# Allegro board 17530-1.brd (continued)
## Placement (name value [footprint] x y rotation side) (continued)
PC4514  SC1U50V3KX-1-GP  [C603H36]  71.53 40.74 270 top
PC4515  SC1500P50V2KX-2-DL-GP  [C402H22]  68.31 59.99 270 top
PC4516  SC10U25V5KX-DL-GP  [C805H58]  92.71 38.61 180 top
PC4517  SC10U25V5KX-DL-GP  [C805H58]  94.74 38.61 180 top
PC4518  SCD1U50V3KX-DL-GP  [C603H35]  92.35 45.06 90 top
PC4519  SC1U50V3KX-1-GP  [C603H36]  89.31 39.73 270 top
PC4520  SC1500P50V2KX-2-DL-GP  [C402H22]  85.22 59.82 270 top
PC4601  SC10U25V5KX-DL-GP  [C805H58]  8.28 79.48 90 top
PC4602  SC10U25V5KX-DL-GP  [C805H58]  8.28 81.64 90 top
PC4603  SCD1U50V3KX-DL-GP  [C603H35]  14.58 79.58 0 top
PC4604  SC1U50V3KX-1-GP  [C603H36]  12.32 74.98 270 top
PC4605  SC1500P50V2KX-2-DL-GP  [C402H22]  16.43 77.9 0 top
PC4606  SC10U25V5KX-DL-GP  [C805H58]  8.56 108.56 90 top
PC4607  SC10U25V5KX-DL-GP  [C805H58]  8.56 110.57 90 top
PC4608  SCD1U50V3KX-DL-GP  [C603H35]  21.77 114.45 270 top
PC4609  SC1U50V3KX-1-GP  [C603H36]  16.74 117.93 180 top
PC4610  SC1500P50V2KX-2-DL-GP  [C402H22]  23.19 108.76 180 top
PC4701  SC1U50V3KX-1-GP  [C603H36]  127.51 41.53 90 top
PC4702  SC10U25V5KX-DL-GP  [C805H58]  127.13 37.85 90 top
PC4703  SC10U25V5KX-DL-GP  [C805H58]  127.13 39.88 90 top
PC4704  SCD1U50V3KX-DL-GP  [C603H35]  134.49 50.8 0 top
PC4705  SC1U50V3KX-1-GP  [C603H36]  114.43 41.15 0 top
PC4706  SC1U50V3KX-1-GP  [C603H36]  133.22 50.8 0 top
PC4707  SC1500P50V2KX-2-DL-GP  [C402H22]  122.94 51.44 90 top
PC4708  SC18P50V2JN-1DLGP  [C402H22]  135 61.87 0 top
PC4801  SC10U10V5KX-2DLGP  [C805H50]  126.11 89.43 90 top
PC4802  SC10U10V5KX-2DLGP  [C805H50]  126.14 87.4 90 top
PC4803  SCD1U16V2KX-3DLGP  [C402H22]  126.29 90.91 90 top
PC4804  SC1U50V3KX-1-GP  [C603H36]  122.66 74.68 180 top
PC4805  SCD047U25V2KX-4-GP  [C402H22]  128.91 75.44 90 top
PC4806  SCD01U50V2KX-1DLGP  [C402H22]  124.97 82.55 270 top
PC4807  SC1KP50V2KX-1DLGP  [C402H22]  128.52 73.94 0 top
PC4808  SC22U6D3V5MX-2DLGP  [C805H54]  125.02 80.06 90 top
PC4809  SC22U6D3V5MX-2DLGP  [C805H54]  125.02 78.03 90 top
PC4810  SCD1U16V2KX-3DLGP  [C402H22]  124.97 81.53 90 top
PC4811  SCD047U25V2KX-4-GP  [C402H22]  129.08 71.53 270 top
PC4812  SC2200P50V2KX-2DLGP  [C402H22]  129.11 72.47 270 top
PC4901  SC10U25V5KX-DL-GP  [C805H58]  22.25 203.24 270 top
PC4902  SC10U25V5KX-DL-GP  [C805H58]  30.2 210.64 90 top
PC4903  SC10U25V5KX-DL-GP  [C805H58]  30.18 212.62 90 top
PC4904  SC10U25V5KX-DL-GP  [C805H58]  22.23 205.49 270 top
PC4905  SC10U25V5KX-DL-GP  [C805H58]  30.2 208.65 90 top
PC4906  SCD1U50V3KX-DL-GP  [C603H35]  17.48 201.96 90 top
PC4907  SCD1U50V3KX-DL-GP  [C603H35]  11.63 198.5 0 top
PC4908  SCD1U50V3KX-DL-GP  [C603H35]  16 210.16 270 top
PC4909  SC1U50V3KX-1-GP  [C603H36]  21.69 177.83 270 top
PC4910  SC1U50V3KX-1-GP  [C603H36]  24.04 231.53 180 top
PC4911  SC1KP50V2KX-1DLGP  [C402H22]  31.88 191.85 90 top
PC4912  SC1KP50V2KX-1DLGP  [C402H22]  26.54 214.88 90 top
PC4913  SCD1U16V2KX-3DLGP  [C402H22]  16.59 204.27 90 top
PC4914  SC22P50V2JN-4DLGP  [C402H22]  7.72 200.46 90 top
PC4915  SC22P50V2JN-4DLGP  [C402H22]  7.06 205.64 0 top
PC4916  SC1U50V3KX-1-GP  [C603H36]  8 204.09 270 top
PC4917  SC1U50V3KX-1-GP  [C603H36]  17.5 203.15 90 top
PC4918  SCD22U10V2KX-2-GP  [C402H22]  10.54 196.39 90 top
PC4919  SCD22U10V2KX-2-GP  [C402H22]  12.14 208.69 180 top
PC5001  SC1U50V3KX-1-GP  [C603H36]  46.63 175.77 90 top
PC5002  SC1U50V3KX-1-GP  [C603H36]  45.85 177.77 180 top
PC5003  SC1U50V3KX-1-GP  [C603H36]  49.58 179.58 270 top
PC5004  SC10U25V5KX-DL-GP  [C805H58]  49.66 187.32 270 top
PC5005  SC10U25V5KX-DL-GP  [C805H58]  49.66 185.29 270 top
PC5006  SC10U25V5KX-DL-GP  [C805H58]  49.66 183.26 270 top
PC5007  SC10U25V5KX-DL-GP  [C805H58]  49.66 181.23 270 top
PC5008  SCD1U50V3KX-DL-GP  [C603H35]  45.36 182.55 0 top
PC5009  SC10U10V5KX-2DLGP  [C805H50]  39.12 183.46 270 top
PC5010  SC1U50V3KX-1-GP  [C603H36]  64.8 174.29 270 top
PC5011  SC10U10V5KX-2DLGP  [C805H50]  36.32 179.2 270 top
PC5012  SC10U10V5KX-2DLGP  [C805H50]  36.32 181.23 270 top
PC5013  SC18P50V2JN-1DLGP  [C402H22]  37.97 174.85 0 top
PC5014  SC1500P50V2KX-2-DL-GP  [C402H22]  55.35 180.57 270 top
PC5015  SCD047U25V2KX-4-GP  [C402H22]  38.58 177.5 0 top
PC5101  SC1U50V3KX-1-GP  [C603H36]  193.17 176.66 90 top
PC5102  SC10U25V5KX-DL-GP  [C805H58]  193.55 168.91 90 top
PC5103  SC10U25V5KX-DL-GP  [C805H58]  193.55 170.94 90 top
PC5104  SC10U25V5KX-DL-GP  [C805H58]  193.55 172.97 90 top
PC5105  SC10U25V5KX-DL-GP  [C805H58]  193.55 175.01 90 top
PC5106  SCD1U50V3KX-DL-GP  [C603H35]  192.53 180.47 90 top
PC5107  SC1U50V3KX-1-GP  [C603H36]  194.56 151.64 90 top
PC5108  SC18P50V2JN-1DLGP  [C402H22]  191.24 188.49 90 top
PC5109  SC1U50V3KX-1-GP  [C603H36]  189.87 180.47 270 top
PC5110  SC1500P50V2KX-2-DL-GP  [C402H22]  183.82 165.79 180 top
PC5201  SC10U10V5KX-2DLGP  [C805H50]  103.38 175.51 270 top
PC5202  SC1U50V3KX-1-GP  [C603H36]  103 173.86 270 top
PC5203  SC10U10V5KX-2DLGP  [C805H50]  116.59 175.77 180 top
PC5204  SC10U10V5KX-2DLGP  [C805H50]  114.55 175.77 180 top
PC5205  SCD1U16V2KX-3DLGP  [C402H22]  104.52 171.83 270 top
PC5206  SC150P50V2JN-3GP  [C402H22]  114.27 172.34 180 top
PG4501  GAP-CLOSE-PWR-3-GP  [GAP-CLOSE-PWR-3]  41.02 44.32 90 bottom
PG4502  GAP-CLOSE-PWR-3-GP  [GAP-CLOSE-PWR-3]  41 45.75 270 bottom
PG4503  GAP-CLOSE-PWR-3-GP  [GAP-CLOSE-PWR-3]  53.62 51.28 135 bottom
PG4504  GAP-CLOSE-PWR-3-GP  [GAP-CLOSE-PWR-3]  54.33 51.97 135 bottom
PG4505  GAP-CLOSE-PWR-3-GP  [GAP-CLOSE-PWR-3]  72.44 55.47 135 bottom
PG4506  GAP-CLOSE-PWR-3-GP  [GAP-CLOSE-PWR-3]  73.2 56.24 135 bottom
PG4507  GAP-CLOSE-PWR-3-GP  [GAP-CLOSE-PWR-3]  97.08 52.27 90 bottom
PG4508  GAP-CLOSE-PWR-3-GP  [GAP-CLOSE-PWR-3]  97.03 53.9 270 bottom
PG4601  GAP-CLOSE-PWR-3-GP  [GAP-CLOSE-PWR-3]  20.95 85.34 0 bottom
PG4602  GAP-CLOSE-PWR-3-GP  [GAP-CLOSE-PWR-3]  22.48 85.34 180 bottom
PG4603  GAP-CLOSE-PWR-3-GP  [GAP-CLOSE-PWR-3]  20.42 96.29 0 bottom
PG4604  GAP-CLOSE-PWR-3-GP  [GAP-CLOSE-PWR-3]  22.3 96.29 180 bottom
PG4701  GAP-CLOSE-PWR-3-GP  [GAP-CLOSE-PWR-3]  133.38 64.26 90 top
PG4901  GAP-CLOSE-PWR-3-GP  [GAP-CLOSE-PWR-3]  23.16 224.48 90 bottom
PG4902  GAP-CLOSE-PWR-3-GP  [GAP-CLOSE-PWR-3]  6.99 199.26 270 top
PG4903  GAP-CLOSE-PWR-2U-GP  [GAP-CLOSE-PWR-2U]  18.21 204.24 0 top
PG5005  GAP-CLOSE-PWR-3-GP  [GAP-CLOSE-PWR-3]  36.58 176.91 0 top
PG5006  GAP-CLOSE-PWR-3-GP  [GAP-CLOSE-PWR-3]  36.58 177.67 0 top
PL4501  COIL-D36UH-19-GP  [RT-D6D3-1D4-103065H394]  42.82 44.93 270 top
PL4502  COIL-D36UH-19-GP  [RT-D6D3-1D4-103065H394]  61.24 49.62 270 top
PL4503  COIL-D36UH-19-GP  [RT-D6D3-1D4-103065H394]  79.57 53.29 270 top
PL4504  COIL-D36UH-19-GP  [RT-D6D3-1D4-103065H394]  98.09 53.16 270 top
PL4601  COIL-D36UH-19-GP  [RT-D6D3-1D4-103065H394]  21.02 87.53 180 top
PL4602  COIL-D36UH-19-GP  [RT-D6D3-1D4-103065H394]  21.18 98.45 180 top
PL4701  IND-D47UH-22-GP-U  [L7066-1830-UH119]  118.11 46.48 270 top
PL4901  IND-2D2UH-356-GP  [RT-D6D6-6D6-108108H426]  20.7 192.53 90 top
PL4902  IND-2D2UH-356-GP  [RT-D6D6-6D6-108108H426]  15.39 220.78 90 top
PL4903  MHC2012S800UBP-GP  [L805H44]  46.79 199.47 270 top
PL4904  MHC2012S800UBP-GP  [L805H44]  46.79 201.5 270 top
PL4905  MHC2012S800UBP-GP  [L805H44]  46.79 203.53 270 top
PL5001  COIL-1D2UH-50-GP  [RT-D6D4-1D9-103072H394]  67.26 179.53 180 top
PL5002  MHC2012S800UBP-GP  [L805H44]  52.02 190.96 180 top
PL5003  MHC2012S800UBP-GP  [L805H44]  54.81 190.96 180 top
PL5101  IND-1D5UH-52-GP  [L115100-2030H158]  190.37 159.13 0 top
PL5104  MHC2012S800UBP-GP  [L805H44]  188.47 175.61 180 top
PL5105  MHC2012S800UBP-GP  [L805H44]  190.75 175.61 180 top
PR4401  2D2R3-1-U-GP  [R603H22]  17.78 67.04 90 top
PR4402  1KR2F-3-GP  [R402H16]  16.66 70.76 0 top
PR4403  26K1R2F-2-GP  [R402H16]  16.99 50.39 0 top
PR4404  100R2F-L1-GP-U  [R402H14]  22.29 67.89 0 top
PR4405  45D3R2F-L-GP  [R402H16]  20.26 67.89 0 top
PR4406  75R2F-2-GP  [R402H16]  21.27 67.89 0 top
PR4407  47R2F-GP  [R402H16]  27.38 62.74 90 top
PR4408  4K02R2F-GP  [R402H16]  27.41 60.76 90 top
PR4409  1KR2F-3-GP  [R402H16]  25.81 62.23 0 top
PR4410  10R2F-L-GP  [R402H14]  20.78 65.61 180 top
PR4411  49D9R2F-GP  [R402H16]  19.66 65.63 180 top
PR4412  100KR2F-L1-GP  [R402H16]  23.62 49.78 270 top
PR4413  10KR2F-2-GP  [R402H16]  20.19 49.5 0 top
PR4414  6K98R2F-GP  [R402H16]  25.15 47.88 180 top
PR4415  100KR2F-L1-GP  [R402H16]  25.15 51.05 0 top
PR4416  100R2F-L1-GP-U  [R402H14]  26.95 63.78 270 top
PR4417  6K98R2F-GP  [R402H16]  26.72 50.62 270 top
PR4418  0R0402-PAD-2-GP  [0R0402-PAD-1]  25.02 63.71 270 top
PR4419  100KR2F-L1-GP  [R402H16]  25.2 52.96 0 top
PR4420  3KR2F-GP  [R402H16]  24.99 66.53 270 top
PR4421  6K98R2F-GP  [R402H16]  27.69 53.31 270 top
PR4422  100KR2F-L1-GP  [R402H16]  25.2 54.86 0 top
PR4423  100R2F-L1-GP-U  [R402H14]  26.9 66.52 90 top
PR4424  10KR2F-2-GP  [R402H16]  19.15 49.5 0 top
PR4425  6K98R2F-GP  [R402H16]  29.26 55.45 180 top
PR4426  100KR2F-L1-GP  [R402H16]  27.43 48.64 0 top
PR4427  100KR2F-L1-GP  [R402H16]  27.79 57.97 90 top
PR4428  270KR2F-GP  [R402H16]  27.79 56.95 270 top
PR4429  100KR2F-L1-GP  [R402H16]  29.59 52.31 270 top
PR4430  30KR2F-GP  [R402H16]  21.87 65.59 180 top
PR4431  NTC-100K-20-GP  [NTC-402H24-U]  39.47 51.66 270 top
PR4432  100KR2F-L1-GP  [R402H16]  29.59 53.32 270 top
PR4433  35K7R2F-GP  [R402H16]  24.51 58.55 180 top
PR4434  100KR2F-L1-GP  [R402H16]  30.56 54.99 180 top
PR4435  10R2F-L-GP  [R402H14]  23.14 47.55 180 top
PR4436  10R2F-L-GP  [R402H14]  26.37 48.97 180 top
PR4437  10R2F-L-GP  [R402H14]  27.69 52.27 270 top
PR4438  10R2F-L-GP  [R402H14]  27.64 54.43 270 top
PR4439  47R2F-GP  [R402H16]  10.08 65.35 270 top
PR4440  4K02R2F-GP  [R402H16]  11.35 62.18 270 top
PR4441  10KR2F-2-GP  [R402H16]  15.93 50.42 0 top
PR4442  1KR2F-3-GP  [R402H16]  10.57 63.86 0 top
PR4443  100KR2F-L1-GP  [R402H16]  11.86 54.13 0 top
PR4444  6K98R2F-GP  [R402H16]  10.59 55.04 0 top
PR4445  100R2F-L1-GP-U  [R402H14]  13.18 70.38 270 top
PR4446  100KR2F-L1-GP  [R402H16]  11.89 52.22 0 top
PR4447  0R0402-PAD-2-GP  [0R0402-PAD-1]  12.4 63.97 90 top
PR4448  6K98R2F-GP  [R402H16]  10.16 51.67 90 top
PR4449  68K1R3F-1-GP  [R603]  9.5 58.14 90 top
PR4450  3K6R2F-GP  [R402H16]  12.32 66.88 90 top
PR4451  100KR2F-L1-GP  [R402H16]  9.4 61.47 270 top
PR4452  261KR2F-GP  [R402H16]  8.86 59.72 0 top
PR4453  68K1R3F-1-GP  [R603]  8.86 56.06 0 top
PR4454  100R2F-L1-GP-U  [R402H14]  13.28 68.05 90 top
PR4455  NTC-100K-20-GP  [NTC-402H24-U]  25.1 82.65 90 top
PR4456  133KR2F-GP  [R402H16]  18.11 49.5 0 top
PR4457  24K9R2F-L-GP  [R402H16]  12.24 58.67 180 top
PR4458  42K2R2F-L-GP  [R402H16]  14.27 66.93 270 top
PR4459  10R2F-L-GP  [R402H14]  10.08 53.14 180 top
PR4460  10R2F-L-GP  [R402H14]  10.74 50.5 90 top
PR4461  75R2F-2-GP  [R402H16]  15.75 66.4 0 top
PR4462  2KR2F-3-GP  [R402H16]  18.16 65.93 90 top
PR4463  499R2F-2-GP  [R402H16]  12.95 49.91 0 top
PR4464  499R2F-2-GP  [R402H16]  22.12 49.48 0 top
PR4465  47K5R2F-GP  [R402H16]  14.88 50.42 0 top
PR4466  NTC-100K-20-GP  [NTC-402H24-U]  40.01 32.89 180 top
PR4467  38K3R2F-GP  [R402H16]  14.48 48.9 90 top
PR4468  NTC-100K-20-GP  [NTC-402H24-U]  12.12 82.17 90 top
PR4469  38K3R2F-GP  [R402H16]  21.67 47.98 270 top
PR4471  20KR2F-L-GP  [R402H16]  17.45 64.85 270 top
PR4501  2D2R5F-2-GP  [R805H24]  33.81 36.32 90 top
PR4503  10KR2J-3-GP  [R402H16]  39.52 38.07 270 top
PR4504  1R5J-2-GP  [R805H24]  39.52 35.79 180 top
PR4505  2D2R5F-2-GP  [R805H24]  32.77 51.56 270 top
PR4506  51R2F-2-GP  [R402H16]  30.76 34.42 90 top
PR4507  2D2R5F-2-GP  [R805H24]  51.97 40.49 90 top
PR4509  10KR2J-3-GP  [R402H16]  57.94 42.9 270 top
PR4510  1R5J-2-GP  [R805H24]  57.94 40.49 180 top
PR4511  2D2R5F-2-GP  [R805H24]  52.81 55.68 270 top
PR4512  51R2F-2-GP  [R402H16]  49.17 39.22 90 top
PR4514  2D2R5F-2-GP  [R805H24]  70.74 45.44 90 top
PR4515  10KR2J-3-GP  [R402H16]  76.48 46.46 270 top
PR4516  1R5J-2-GP  [R805H24]  76.48 44.04 180 top
PR4517  2D2R5F-2-GP  [R805H24]  71.09 60.53 270 top
PR4518  51R2F-2-GP  [R402H16]  68.86 43.92 90 top
PR4520  2D2R5F-2-GP  [R805H24]  89.18 44.68 90 top
PR4521  10KR2J-3-GP  [R402H16]  94.77 46.33 270 top
PR4522  1R5J-2-GP  [R805H24]  94.77 43.92 180 top
PR4523  2D2R5F-2-GP  [R805H24]  88.01 59.82 270 top
PR4524  51R2F-2-GP  [R402H16]  85.7 43 90 top
PR4525  2D2R5F-2-GP  [R805H24]  31.09 32.87 90 top
PR4526  2D2R5F-2-GP  [R805H24]  49.05 37.44 90 top
PR4527  2D2R5F-2-GP  [R805H24]  71.63 38.99 270 top
PR4528  2D2R5F-2-GP  [R805H24]  86.13 41.38 90 top
PR4601  2D2R5F-2-GP  [R805H24]  11.96 79.83 90 top
PR4603  10KR2J-3-GP  [R402H16]  14.15 90.32 180 top
PR4604  1R5J-2-GP  [R805H24]  11.73 90.32 90 top
PR4605  2D2R5F-2-GP  [R805H24]  16.21 80.77 0 top
PR4606  51R2F-2-GP  [R402H16]  10.46 73.99 180 top
PR4608  2D2R5F-2-GP  [R805H24]  21.62 116.89 0 top
PR4609  10KR2J-3-GP  [R402H16]  13.87 108.18 90 top
PR4610  1R5J-2-GP  [R805H24]  13.84 110.59 0 top
PR4611  2D2R5F-2-GP  [R805H24]  23.16 105.94 180 top
PR4612  51R2F-2-GP  [R402H16]  19.33 120.45 0 top
PR4613  2D2R5F-2-GP  [R805H24]  14.61 72.75 270 top
PR4614  2D2R5F-2-GP  [R805H24]  17.81 121.72 0 top
PR4701  GAP-CLOSE-PWR-3-GP  [GAP-CLOSE-PWR-3]  123.75 41.1 180 top
PR4702  GAP-CLOSE-PWR-3-GP  [GAP-CLOSE-PWR-3]  123.75 40.34 180 top
PR4703  GAP-CLOSE-PWR-3-GP  [GAP-CLOSE-PWR-3]  123.75 39.57 180 top
PR4704  GAP-CLOSE-PWR-3-GP  [GAP-CLOSE-PWR-3]  123.75 38.81 180 top
PR4705  GAP-CLOSE-PWR-3-GP  [GAP-CLOSE-PWR-3]  123.75 38.05 180 top
PR4706  GAP-CLOSE-PWR-3-GP  [GAP-CLOSE-PWR-3]  123.75 37.29 180 top
PR4707  2D2R5J-1-GP  [R805H24]  118.75 41.53 270 top
PR4708  40K2R2F-GP  [R402H16]  137.67 59.69 180 top
PR4709  2D2R5J-1-GP  [R805H24]  136.14 50.8 0 top
PR4710  10KR2J-3-GP  [R402H16]  121.16 41.53 0 top
PR4711  470KR2F-GP  [R402H16]  133.99 61.87 180 top
PR4712  2D2R5J-1-GP  [R805H24]  131.57 50.55 0 top
PR4713  2D2R5J-1-GP  [R805H24]  120.14 51.44 90 top
PR4714  4K87R2F-GP  [R402H16]  136.14 61.87 0 top
PR4715  10R2F-L-GP  [R402H14]  135 63.98 90 top
PR4716  10KR2F-2-GP  [R402H16]  137.29 61.87 180 top
PR4717  10R2F-L-GP  [R402H14]  136.91 63.98 90 top
PR4801  GAP-CLOSE-PWR-3-GP  [GAP-CLOSE-PWR-3]  120.32 92.25 90 top
PR4802  GAP-CLOSE-PWR-3-GP  [GAP-CLOSE-PWR-3]  121.08 92.25 90 top
PR4803  GAP-CLOSE-PWR-3-GP  [GAP-CLOSE-PWR-3]  121.97 92.25 90 top
PR4804  GAP-CLOSE-PWR-3-GP  [GAP-CLOSE-PWR-3]  122.73 92.25 90 top
PR4805  GAP-CLOSE-PWR-3-GP  [GAP-CLOSE-PWR-3]  125.02 92.25 90 top
PR4806  GAP-CLOSE-PWR-3-GP  [GAP-CLOSE-PWR-3]  123.49 92.25 90 top
PR4807  GAP-CLOSE-PWR-3-GP  [GAP-CLOSE-PWR-3]  125.78 92.25 90 top
PR4808  10R2F-L-GP  [R402H14]  122.66 72.26 180 top
PR4809  GAP-CLOSE-PWR-3-GP  [GAP-CLOSE-PWR-3]  124.26 92.25 90 top
PR4810  100R5J-4-GP  [R805H24]  126.24 84.61 90 top
PR4811  2K2R2F-GP  [R402H16]  129.54 73.94 0 top
PR4812  0R0402-PAD-2-GP  [0R0402-PAD-1]  124.26 70.92 270 top
PR4813  10R2F-L-GP  [R402H14]  129.03 69.37 90 top
PR4814  4K7R2F-GP  [R402H16]  129.01 70.51 90 top
PR4815  10R2F-L-GP  [R402H14]  117.22 90.42 180 top
PR4816  24KR2F-GP  [R402H16]  126.39 70.94 270 top
PR4901  GAP-CLOSE-PWR-3-GP  [GAP-CLOSE-PWR-3]  28.32 179.45 180 top
PR4902  GAP-CLOSE-PWR-3-GP  [GAP-CLOSE-PWR-3]  28.32 180.21 180 top
PR4903  GAP-CLOSE-PWR-3-GP  [GAP-CLOSE-PWR-3]  28.32 180.97 180 top
PR4904  GAP-CLOSE-PWR-3-GP  [GAP-CLOSE-PWR-3]  28.32 181.74 180 top
PR4905  GAP-CLOSE-PWR-3-GP  [GAP-CLOSE-PWR-3]  28.32 182.5 180 top
PR4906  GAP-CLOSE-PWR-3-GP  [GAP-CLOSE-PWR-3]  28.32 183.26 180 top
PR4908  GAP-CLOSE-PWR-3-GP  [GAP-CLOSE-PWR-3]  28.32 178.69 180 top
PR4910  GAP-CLOSE-PWR-3-GP  [GAP-CLOSE-PWR-3]  28.32 189.36 180 top
PR4912  GAP-CLOSE-PWR-3-GP  [GAP-CLOSE-PWR-3]  28.32 188.59 180 top
PR4914  GAP-CLOSE-PWR-3-GP  [GAP-CLOSE-PWR-3]  28.32 187.83 180 top
PR4916  GAP-CLOSE-PWR-3-GP  [GAP-CLOSE-PWR-3]  28.32 187.07 180 top
PR4918  GAP-CLOSE-PWR-3-GP  [GAP-CLOSE-PWR-3]  28.32 186.31 180 top
PR4920  GAP-CLOSE-PWR-3-GP  [GAP-CLOSE-PWR-3]  28.32 185.55 180 top
PR4922  GAP-CLOSE-PWR-3-GP  [GAP-CLOSE-PWR-3]  28.32 184.78 180 top
PR4924  GAP-CLOSE-PWR-3-GP  [GAP-CLOSE-PWR-3]  28.32 184.02 180 top
PR4925  GAP-CLOSE-PWR-3-GP  [GAP-CLOSE-PWR-3]  27.43 231.14 90 top
PR4927  GAP-CLOSE-PWR-3-GP  [GAP-CLOSE-PWR-3]  26.67 231.14 90 top
PR4929  GAP-CLOSE-PWR-3-GP  [GAP-CLOSE-PWR-3]  25.91 231.14 90 top
PR4932  2D2R5J-1-GP  [R805H24]  16.79 200.33 270 top
PR4933  GAP-CLOSE-PWR-3-GP  [GAP-CLOSE-PWR-3]  28.96 231.14 90 top
PR4934  GAP-CLOSE-PWR-3-GP  [GAP-CLOSE-PWR-3]  28.19 231.14 90 top
PR4936  GAP-CLOSE-PWR-3-GP  [GAP-CLOSE-PWR-3]  25.15 231.14 90 top
PR4937  GAP-CLOSE-PWR-3-GP  [GAP-CLOSE-PWR-3]  29.72 231.14 90 top
PR4938  GAP-CLOSE-PWR-3-GP  [GAP-CLOSE-PWR-3]  30.48 231.14 90 top
PR4939  GAP-CLOSE-PWR-3-GP  [GAP-CLOSE-PWR-3]  31.24 231.14 90 top
PR4940  GAP-CLOSE-PWR-3-GP  [GAP-CLOSE-PWR-3]  32 231.14 90 top
PR4941  2D2R5J-1-GP  [R805H24]  18.92 207.37 0 top
PR4942  2D2R5J-1-GP  [R805H24]  13.21 197.46 180 top
PR4943  2D2R5J-1-GP  [R805H24]  16.03 208.58 90 top
PR4944  2D2R5J-1-GP  [R805H24]  33.02 199.97 270 top
PR4945  GAP-CLOSE-PWR-3-GP  [GAP-CLOSE-PWR-3]  32.77 231.14 90 top
PR4946  GAP-CLOSE-PWR-3-GP  [GAP-CLOSE-PWR-3]  32.77 231.14 90 bottom
PR4947  GAP-CLOSE-PWR-3-GP  [GAP-CLOSE-PWR-3]  32 231.14 90 bottom
PR4948  GAP-CLOSE-PWR-3-GP  [GAP-CLOSE-PWR-3]  31.24 231.14 90 bottom
PR4949  GAP-CLOSE-PWR-3-GP  [GAP-CLOSE-PWR-3]  30.48 231.14 90 bottom
PR4950  2D2R5J-1-GP  [R805H24]  29.03 191.34 90 top
PR4951  2D2R5J-1-GP  [R805H24]  23.75 214.88 90 top
PR4952  78K7R2F-GP  [R402H16]  8 199.01 0 top
PR4953  62KR2F-GP  [R402H16]  10.16 208.66 180 top
PR4954  6K65R2F-GP  [R402H16]  7.72 201.42 90 top
PR4955  15K4R2F-GP  [R402H16]  8 205.61 0 top
PR4956  10KR2F-2-GP  [R402H16]  8.38 202.44 270 top
PR4957  10KR2F-2-GP  [R402H16]  9.02 205.61 180 top
PR4958  100KR2J-1-GP  [R402H16]  10.46 198.88 0 top
PR4959  10KR2J-3-GP  [R402H16]  10.03 197.36 270 top
PR4960  100KR2F-L1-GP  [R402H16]  13.11 209.65 0 top
PR4961  10KR2J-3-GP  [R402H16]  11.3 195.38 90 top
PR4962  28KR2F-GP  [R402H16]  11.18 208.66 180 top
PR5001  2D2R2F-GP  [R402H16]  46.74 174.62 270 top
PR5002  0R0603-PAD-2-GP-U  [0R0603-PAD-1-U]  47.07 177.77 180 top
PR5003  205KR2F-GP  [R402H16]  45.42 180.21 180 top
PR5004  10KR2J-3-GP  [R402H16]  60.15 186.31 0 top
PR5005  2D2R5J-1-GP  [R805H24]  61.67 186.64 0 top
PR5006  GAP-CLOSE-PWR-3-GP  [GAP-CLOSE-PWR-3]  78.74 173.05 0 top
PR5007  2D2R5J-1-GP  [R805H24]  42.67 183.51 90 top
PR5008  GAP-CLOSE-PWR-3-GP  [GAP-CLOSE-PWR-3]  78.74 173.81 0 top
PR5009  620KR2F-GP  [R402H16]  43.69 174.75 180 top
PR5010  GAP-CLOSE-PWR-3-GP  [GAP-CLOSE-PWR-3]  78.74 174.57 0 top
PR5011  GAP-CLOSE-PWR-3-GP  [GAP-CLOSE-PWR-3]  78.74 175.34 0 top
PR5012  GAP-CLOSE-PWR-3-GP  [GAP-CLOSE-PWR-3]  78.74 176.1 0 top
PR5013  GAP-CLOSE-PWR-3-GP  [GAP-CLOSE-PWR-3]  78.74 176.86 0 top
PR5014  0R0805-PAD-2-GP-U  [0R0805-PAD-1-U]  41.4 185.55 270 top
PR5015  GAP-CLOSE-PWR-3-GP  [GAP-CLOSE-PWR-3]  71.5 173.69 270 top
PR5016  2D2R5J-1-GP  [R805H24]  58.14 180.57 270 top
PR5017  GAP-CLOSE-PWR-3-GP  [GAP-CLOSE-PWR-3]  72.26 173.69 270 top
PR5018  GAP-CLOSE-PWR-3-GP  [GAP-CLOSE-PWR-3]  73.03 173.69 270 top
PR5019  0R0402-PAD-2-GP  [0R0402-PAD-1]  64.91 173.14 90 top
PR5020  GAP-CLOSE-PWR-3-GP  [GAP-CLOSE-PWR-3]  73.79 173.69 270 top
PR5021  GAP-CLOSE-PWR-3-GP  [GAP-CLOSE-PWR-3]  74.55 173.69 270 top
PR5022  GAP-CLOSE-PWR-3-GP  [GAP-CLOSE-PWR-3]  75.31 173.69 270 top
PR5023  GAP-CLOSE-PWR-3-GP  [GAP-CLOSE-PWR-3]  76.07 173.69 270 top
PR5024  15K8R2F-GP  [R402H16]  38.96 174.88 0 top
PR5025  20KR2F-L-GP  [R402H16]  40.59 174.24 0 top
PR5026  GAP-CLOSE-PWR-3-GP  [GAP-CLOSE-PWR-3]  70.59 173.69 270 top
PR5027  GAP-CLOSE-PWR-3-GP  [GAP-CLOSE-PWR-3]  66.93 173.69 270 top
PR5028  GAP-CLOSE-PWR-3-GP  [GAP-CLOSE-PWR-3]  68.76 173.69 270 top
PR5029  GAP-CLOSE-PWR-3-GP  [GAP-CLOSE-PWR-3]  69.67 173.69 270 top
PR5030  GAP-CLOSE-PWR-3-GP  [GAP-CLOSE-PWR-3]  67.84 173.69 270 top
PR5107  10KR2J-3-GP  [R402H16]  194.92 183.92 90 top
PR5108  2D2R5J-1-GP  [R805H24]  193.55 166.88 90 top
PR5109  10KR2J-3-GP  [R402H16]  190.75 166.37 270 top
PR5110  2D2R5J-1-GP  [R805H24]  195.2 180.64 180 top
PR5111  56KR2F-GP  [R402H16]  195.76 187.38 180 top
PR5112  470KR2F-GP  [R402H16]  189.33 186.26 180 top
PR5113  2D2R5J-1-GP  [R805H24]  183.77 162.94 180 top
PR5114  4K87R2F-GP  [R402H16]  191.29 189.48 90 top
PR5115  2D2R5J-1-GP  [R805H24]  188.85 183.01 180 top
PR5116  10KR2F-2-GP  [R402H16]  191.29 190.53 270 top
PR5117  GAP-CLOSE-PWR-3-GP  [GAP-CLOSE-PWR-3]  187.58 150.37 180 top
PR5118  GAP-CLOSE-PWR-3-GP  [GAP-CLOSE-PWR-3]  187.58 151.89 180 top
PR5119  GAP-CLOSE-PWR-3-GP  [GAP-CLOSE-PWR-3]  187.58 151.13 180 top
PR5120  GAP-CLOSE-PWR-3-GP  [GAP-CLOSE-PWR-3]  187.58 151.38 180 bottom
PR5121  GAP-CLOSE-PWR-3-GP  [GAP-CLOSE-PWR-3]  187.58 150.62 180 bottom
PR5122  GAP-CLOSE-PWR-3-GP  [GAP-CLOSE-PWR-3]  187.58 149.86 180 bottom
PR5123  GAP-CLOSE-PWR-3-GP  [GAP-CLOSE-PWR-3]  187.58 149.1 180 bottom
PR5124  GAP-CLOSE-PWR-3-GP  [GAP-CLOSE-PWR-3]  187.58 148.34 180 bottom
PR5125  GAP-CLOSE-PWR-3-GP  [GAP-CLOSE-PWR-3]  187.58 147.57 180 bottom
PR5126  GAP-CLOSE-PWR-3-GP  [GAP-CLOSE-PWR-3]  187.58 152.15 180 bottom
PR5127  GAP-CLOSE-PWR-3-GP  [GAP-CLOSE-PWR-3]  187.58 152.91 180 bottom
PR5128  GAP-CLOSE-PWR-3-GP  [GAP-CLOSE-PWR-3]  187.58 153.67 180 bottom
PR5129  GAP-CLOSE-PWR-3-GP  [GAP-CLOSE-PWR-3]  187.58 154.43 180 bottom
PR5130  GAP-CLOSE-PWR-3-GP  [GAP-CLOSE-PWR-3]  187.58 155.19 180 bottom
PR5131  GAP-CLOSE-PWR-3-GP  [GAP-CLOSE-PWR-3]  187.58 155.96 180 bottom
PR5132  GAP-CLOSE-PWR-3-GP  [GAP-CLOSE-PWR-3]  187.58 156.72 180 bottom
PR5133  GAP-CLOSE-PWR-3-GP  [GAP-CLOSE-PWR-3]  187.58 148.08 180 top
PR5134  GAP-CLOSE-PWR-3-GP  [GAP-CLOSE-PWR-3]  187.58 148.84 180 top
PR5135  GAP-CLOSE-PWR-3-GP  [GAP-CLOSE-PWR-3]  187.58 149.61 180 top
PR5201  0R0805-PAD-2-GP-U  [0R0805-PAD-1-U]  103.38 177.55 270 top
PR5202  10KR2F-2-GP  [R402H16]  100.33 175.26 0 top
PR5203  0R0805-PAD-2-GP-U  [0R0805-PAD-1-U]  116.81 172.09 0 top
PR5204  0R0402-PAD-2-GP  [0R0402-PAD-1]  104.57 170.81 270 top
PR5205  21K5R2F-GP  [R402H16]  115.29 172.34 0 top
PR5206  10KR2F-2-GP  [R402H16]  114.86 170.76 270 top
PT4501  E270U16VM-16-GP  [ECAP-138D8-UH355]  71.22 33.2 270 top
PT4502  E820U2D5VM-6-GP  [ECAP-100D6D3H375]  52.32 60.58 270 top
PT4503  E820U2D5VM-6-GP  [ECAP-100D6D3H375]  59.05 64.64 270 top
PT4504  E270U16VM-16-GP  [ECAP-138D8-UH355]  81.84 33.99 270 top
PT4505  E820U2D5VM-6-GP  [ECAP-100D6D3H375]  66.93 64.64 180 top
PT4506  E270U16VM-16-GP  [ECAP-138D8-UH355]  58.8 30.48 270 top
PT4507  E820U2D5VM-6-GP  [ECAP-100D6D3H375]  75.23 64.62 180 top
PT4508  E820U2D5VM-6-GP  [ECAP-100D6D3H375]  83.44 64.52 180 top
PT4601  E270U16VM-16-GP  [ECAP-138D8-UH355]  10.16 96.16 180 top
PT4602  E820U2D5VM-6-GP  [ECAP-100D6D3H375]  31.11 76.96 180 top
PT4603  E820U2D5VM-6-GP  [ECAP-100D6D3H375]  31.37 100.71 180 top
PT4604  E820U2D5VM-6-GP  [ECAP-100D6D3H375]  31.11 92.84 180 top
PT4605  E820U2D5VM-6-GP  [ECAP-100D6D3H375]  31.11 84.84 180 top
PT4701  E820U2D5VM-6-GP  [ECAP-100D6D3H375]  109.47 42.04 180 top
PT4702  E820U2D5VM-6-GP  [ECAP-100D6D3H375]  109.52 49.99 180 top
PT4801  E820U2D5VM-6-GP  [ECAP-100D6D3H375]  119.15 78.71 180 top
PT4901  E270U16VM-16-GP  [ECAP-138D8-UH355]  40.2 199.2 180 top
PT4902  SE220U6D3VM-3GP  [SE3116H241]  22.23 182.25 270 top
PT4903  SE220U6D3VM-3GP  [SE3116H241]  27 226.38 90 top
PT5001  E820U2D5VM-6-GP  [ECAP-100D6D3H375]  77.72 180.97 270 top
PT5101  E820U2D5VM-6-GP  [ECAP-100D6D3H375]  192.15 146.89 180 top
PU4401  NCP81220MNTXG-4-GP  [QFN52J6-G4D8-UH40]  18.44 58.17 0 top
PU4501  AONS36358-1-GP  [PPAK-8P-5262H40]  43.84 33.76 180 top
PU4502  NCP81258MNTBG-GP  [DFN8G2-G1309-UH40]  34.95 33.76 90 top
PU4503  AONS36356-GP  [PPAK-8P-5262H40]  35.33 47.22 270 top
PU4504  AONS36356-GP  [PPAK-8P-5262H40]  35.33 40.61 270 top
PU4505  AONS36358-1-GP  [PPAK-8P-5262H40]  62.26 38.46 180 top
PU4506  NCP81258MNTBG-GP  [DFN8G2-G1309-UH40]  53.11 37.95 90 top
PU4507  AONS36356-GP  [PPAK-8P-5262H40]  53.75 51.41 270 top
PU4508  AONS36356-GP  [PPAK-8P-5262H40]  53.75 44.81 270 top
PU4509  AONS36358-1-GP  [PPAK-8P-5262H40]  80.8 42.15 180 top
PU4510  NCP81258MNTBG-GP  [DFN8G2-G1309-UH40]  72.16 42.9 90 top
PU4511  AONS36356-GP  [PPAK-8P-5262H40]  72.03 56.21 270 top
PU4512  AONS36356-GP  [PPAK-8P-5262H40]  72.03 49.68 270 top
PU4513  AONS36358-1-GP  [PPAK-8P-5262H40]  99.06 42.04 180 top
PU4514  NCP81258MNTBG-GP  [DFN8G2-G1309-UH40]  90.19 42 90 top
PU4515  AONS36356-GP  [PPAK-8P-5262H40]  90.58 48.92 270 top
PU4516  AONS36356-GP  [PPAK-8P-5262H40]  90.58 55.47 270 top
PU4601  AONS36358-1-GP  [PPAK-8P-5262H40]  9.82 85.99 90 top
PU4602  NCP81258MNTBG-GP  [DFN8G2-G1309-UH40]  12.04 77.11 90 top
PU4603  AONS36356-GP  [PPAK-8P-5262H40]  20.66 79.85 0 top
PU4604  AONS36358-1-GP  [PPAK-8P-5262H40]  9.82 104.2 90 top
PU4605  NCP81258MNTBG-GP  [DFN8G2-G1309-UH40]  18.95 117.4 0 top
PU4606  AONS36356-GP  [PPAK-8P-5262H40]  18.3 105.96 180 top
PU4701  RT8237CZQW-2-GP  [DFN10G3-G265175H32]  135 57.4 0 top
PU4702  FDMS3600-02-RJK0215-COLAY-GP  [PPAK-8P-G5324H44-COLAY]  125.86 46.35 0 top
PU4801  APL5611ACI-TRG-GP  [SOT-6H58]  125.35 74.17 0 top
PU4802  AONS36358-1-GP  [PPAK-8P-5262H40]  121.06 88.29 0 top
PU4901  AONS36358-1-GP  [PPAK-8P-5262H40]  27.81 204.09 0 top
PU4902  RT6575DGQW-GP  [QFN20-G1D75H32]  12.45 203.84 90 top
PU4903  AONS36358-1-GP  [PPAK-8P-5262H40]  25.15 210.57 270 top
PU4904  AONS36356-GP  [PPAK-8P-5262H40]  30.33 195.61 90 top
PU4905  AONS36356-GP  [PPAK-8P-5262H40]  25.15 219.2 90 top
PU5001  RT8231AGQW-GP  [QFN20-G1D75H32]  41.53 179.07 90 top
PU5002  AONS36358-1-GP  [PPAK-8P-5262H40]  54.66 184.86 90 top
PU5003  AONS36356-GP  [PPAK-8P-5262H40]  57.35 176.3 270 top
PU5101  RT8237CZQW-2-GP  [DFN10G3-G265175H32]  191.9 184.78 0 top
PU5102  FDMS3600-02-RJK0215-COLAY-GP  [PPAK-8P-G5324H44-COLAY]  187.71 170.05 90 top
PU5201  APL5930KAI-TRG-1-GP  [SOIC8-G3530H63]  109.47 173.99 90 top
PWRSW1  JWT-CONN8D-SFP3-GP-U  [A2003WV0-2LX4PA-6T-Z-U]  18.8 233.75 0 top
Q801  AO3418L-GP  [SOT23DGS2D8H50]  182.83 155.04 270 top
Q802  2N7002KDW-1-GP  [SOT-363H44]  181.11 171.85 0 top
Q2001  LMBT3906LT1G-1-GP  [SOT23CBE2D4H44]  194.06 21.16 0 top
Q2401  MMDT3904-2-GP  [SOT-363-1H44]  156.31 38.84 0 top
Q2402  MMDT3904-2-GP  [SOT-363-1H44]  158.06 33.58 270 top
Q2403  LMBT3904LT1G-GP  [SOT23CBE2D4H44]  148.77 171.68 90 top
Q2404  LMBT3904LT1G-GP  [SOT23CBE2D4H44]  104.32 45.95 0 top
Q2405  MMDT3904-2-GP  [SOT-363-1H44]  159.46 38.86 180 top
Q2406  MMDT3904-2-GP  [SOT-363-1H44]  167.79 39.93 270 top
Q2407  2N7002K-2-GP  [SOT23DGS2D4H44]  159.38 15.37 90 top
Q2408  MMDT3904-2-GP  [SOT-363-1H44]  172.42 7.95 90 top
Q2409  LMBT3904LT1G-GP  [SOT23CBE2D4H44]  132.21 36.83 0 top
Q2701  LMBT3906LT1G-1-GP  [SOT23CBE2D4H44]  55.24 265.43 270 top
Q2702  LMBT3906LT1G-1-GP  [SOT23CBE2D4H44]  64.9 244.35 0 top
Q2703  LMBT3906LT1G-1-GP  [SOT23CBE2D4H44]  67.41 240.46 180 top
Q2704  LMBT3906LT1G-1-GP  [SOT23CBE2D4H44]  63.83 240.46 0 top
Q2901  MMDT3904-2-GP  [SOT-363-1H44]  59.82 270.89 90 top
Q3001  MMDT3904-2-GP  [SOT-363-1H44]  27.94 21.84 180 top
Q3801  MBT3904DW1T1G-2-GP  [SOT-363H44]  78.87 262.64 0 top
Q4002  MMDT3904-2-GP  [SOT-363-1H44]  97.54 171.96 90 top
Q4201  AONS36358-1-GP  [PPAK-8P-5262H40]  32.74 185.39 180 top
Q4205  LMBT3904LT1G-GP  [SOT23CBE2D4H44]  188.47 189.87 180 top
Q4206  DMP2130L-7-GP  [SOT23DGS2D4H48]  21.82 38.68 270 top
Q4207  LMBT3904LT1G-GP  [SOT23CBE2D4H44]  26.01 38.58 0 top
Q5601  2N7002KDW-1-GP  [SOT-363H44]  65.53 20.57 180 top
Q5901  AO3418L-GP  [SOT23DGS2D8H50]  46.46 26.02 270 top
Q6401  2N7002KDW-1-GP  [SOT-363H44]  6.98 227.9 90 top
Q9101  2N7002K-2-GP  [SOT23DGS2D4H44]  162.81 165.48 90 top
Q9102  LMBT3904LT1G-GP  [SOT23CBE2D4H44]  96.88 175.39 270 top
Q9103  2N7002KDW-1-GP  [SOT-363H44]  63.57 233.78 0 top
R301  24D9R2F-L-GP  [R402H16]  82.98 93.4 0 top
R401  56D2R2F-GP  [R402H16]  26.47 71.7 90 top
R402  100R2F-L1-GP-U  [R402H14]  127.08 58.8 90 top
R403  100R2F-L1-GP-U  [R402H14]  26.52 72.77 90 top
R404  1KR2F-3-GP  [R402H16]  15.72 68.36 0 top
R405  220R2F-GP  [R402H16]  28.55 71.7 90 top
R407  0R0402-PAD-2-GP  [0R0402-PAD-1]  28.55 70.66 90 top
R408  0R0402-PAD-2-GP  [0R0402-PAD-1]  28.55 72.82 90 top
R409  499R2F-2-GP  [R402H16]  30.23 69.6 90 top
R410  0R0402-PAD-2-GP  [0R0402-PAD-1]  124.08 58.42 270 top
R411  0R0402-PAD-2-GP  [0R0402-PAD-1]  124.08 59.56 90 top
R412  0R0402-PAD-2-GP  [0R0402-PAD-1]  124.08 57.4 90 top
R413  10KR2J-3-GP  [R402H16]  23.5 174.24 180 top
R414  100KR2J-1-GP  [R402H16]  23.24 172.34 0 top
R415  51R2F-2-GP  [R402H16]  124.08 60.58 90 top
R416  10KR2J-3-GP  [R402H16]  20.45 170.56 270 top
R417  0R0402-PAD-2-GP  [0R0402-PAD-1]  156.84 107.82 225 top
R418  49D9R2F-GP  [R402H16]  81.92 93.34 180 top
R419  6K04R2F-GP  [R402H16]  127 56.52 270 top
R420  2K8R2F-GP  [R402H16]  127 57.66 90 top
R421  20R2F-GP  [R402H16]  124.08 61.59 270 top
R422  10KR2J-3-GP  [R402H16]  70.21 103.07 270 top
R423  1K5R2F-2-GP  [R402H16]  122.1 55.3 90 top
R424  1KR2J-1-GP  [R402H16]  119.38 53.57 90 top
R425  1KR2J-1-GP  [R402H16]  124.26 69.82 270 top
R426  1KR2J-1-GP  [R402H16]  122.1 54.23 270 top
R427  51R2F-2-GP  [R402H16]  157.3 99.64 0 top
R601  2R2F-GP  [R402H16]  10.41 173.89 180 top
R602  24D9R2F-L-GP  [R402H16]  8.33 170.43 90 top
R701  24D9R2F-L-GP  [R402H16]  84.02 93.4 180 top
R702  20R2J-3-GP  [R402H16]  118.66 94.7 135 top
R801  0R0402-PAD-2-GP  [0R0402-PAD-1]  85.04 105.31 90 bottom
R802  49D9R2F-GP  [R402H16]  28.55 64.97 180 top
R803  0R3J-0-U-GP  [R603H22]  182.78 149.33 270 top
R804  47KR2J-2-GP  [R402H16]  186.33 175.34 0 top
R805  10KR2J-3-GP  [R402H16]  181.13 165.51 0 top
R806  100KR2J-1-GP  [R402H16]  182.14 165.51 0 top
R807  100KR2J-1-GP  [R402H16]  186.44 176.82 270 top
R808  4K7R2J-2-GP  [R402H16]  181.28 158.27 90 top
R809  0R0402-PAD-2-GP  [0R0402-PAD-1]  178.33 172.91 180 top
R810  100KR2J-1-GP  [R402H16]  183.15 173.03 180 top
R901  20R2F-GP  [R402H16]  127.13 64.52 270 top
R902  0R0402-PAD-2-GP  [0R0402-PAD-1]  87.1 86.92 0 bottom
R903  0R0402-PAD-2-GP  [0R0402-PAD-1]  93.96 117.83 135 bottom
R1101  240R2F-1-GP  [R402H16]  83.82 171.83 0 top
R1102  0R2J-2-GP  [R402H16]  12.45 154.05 270 top
R1103  1KR2F-3-GP  [R402H16]  11.48 174.04 180 top
R1104  470R2J-2-GP  [R402H16]  75.82 170.43 90 top
R1105  0R0402-PAD-2-GP  [0R0402-PAD-1]  13.56 174.04 0 top
R1106  1KR2F-3-GP  [R402H16]  12.52 174.04 0 top
R1201  240R2F-1-GP  [R402H16]  84.96 171.83 0 top
R1202  0R2J-2-GP  [R402H16]  12.93 170.87 0 top
R1203  1KR2F-3-GP  [R402H16]  17.78 173.18 180 top
R1204  2R2F-GP  [R402H16]  14.61 173.18 0 top
R1205  0R0402-PAD-2-GP  [0R0402-PAD-1]  15.65 173.18 0 top
R1206  1KR2F-3-GP  [R402H16]  16.71 173.18 0 top
R1207  24D9R2F-L-GP  [R402H16]  17.81 174.73 90 top
R1502  10KR2J-3-GP  [R402H16]  157.1 146.58 90 top
R1503  8K2R2F-1-GP  [R402H16]  160.35 146.43 180 top
R1504  33R2J-2-GP  [R402H16]  167 10.29 180 top
R1506  10KR2J-3-GP  [R402H16]  169.16 62.1 90 top
R1507  1MR2J-1-GP  [R402H16]  165.64 150.62 270 top
R1508  8K2R2F-1-GP  [R402H16]  167.31 131.67 270 top
R1509  10KR2J-3-GP  [R402H16]  159.89 105.03 180 top
R1510  10KR2J-3-GP  [R402H16]  20.19 238.48 0 top
R1511  47KR2J-2-GP  [R402H16]  167.34 109.7 270 top
R1512  150R2F-1-GP  [R402H16]  167.31 110.74 90 top
R1513  100R2F-L1-GP-U  [R402H14]  137.67 118.11 0 top
R1514  200R2F-L-GP  [R402H16]  167.28 111.79 90 top
R1515  100KR2J-1-GP  [R402H16]  173.61 171.45 270 top
R1516  100KR2J-1-GP  [R402H16]  168.07 10.29 0 top
R1601  10KR2J-3-GP  [R402H16]  163.35 154.13 180 top
R1604  10KR2J-3-GP  [R402H16]  159.97 152.99 270 top
R1605  10KR2J-3-GP  [R402H16]  159.26 146.38 180 top
R1606  10KR2J-3-GP  [R402H16]  164.11 148.67 180 top
R1607  10KR2J-3-GP  [R402H16]  163.6 146.33 180 top
R1609  113R2F-GP  [R402H16]  140.26 107.85 0 top
R1610  10KR2J-3-GP  [R402H16]  139.24 107.85 0 top
R1611  1KR2J-1-GP  [R402H16]  141.27 107.85 0 top
R1701  0R0402-PAD-2-GP  [0R0402-PAD-1]  153.04 144.58 0 top
R1702  0R0402-PAD-2-GP  [0R0402-PAD-1]  153.03 142.67 0 top
R1703  1KR2J-1-GP  [R402H16]  150.57 104.24 270 top
R1704  10KR2J-3-GP  [R402H16]  160.02 142.95 90 top
R1705  10KR2J-3-GP  [R402H16]  161.42 146.43 180 top
R1706  10KR2J-3-GP  [R402H16]  154.05 144.58 180 top
R1708  1KR2J-1-GP  [R402H16]  152.81 107.95 0 top
R1709  10KR2J-3-GP  [R402H16]  53.87 221.21 270 top
R1710  619R2F-L1-GP  [R402H16]  150.32 107.98 0 top
R1711  30R2J-1-GP  [R402H16]  152.94 105.41 0 top
R1712  10KR2J-3-GP  [R402H16]  34.62 237.34 270 top
R1713  10KR2J-3-GP  [R402H16]  152.07 146.58 270 top
R1714  10KR2J-3-GP  [R402H16]  152.07 147.65 270 top
R1801  10KR2J-3-GP  [R402H16]  32.64 224.16 0 top
R1802  60D4R2F-GP  [R402H16]  148.46 108.43 90 top
R1803  10KR2J-3-GP  [R402H16]  144.2 18.06 0 top
R1805  10KR2J-3-GP  [R402H16]  135.23 4.22 270 top
R1806  10KR2J-3-GP  [R402H16]  175.39 55.63 180 top
R1807  10KR2J-3-GP  [R402H16]  176.12 59.46 0 top
R1809  10KR2J-3-GP  [R402H16]  169.14 57.76 90 top
R1812  200KR2F-L-GP  [R402H16]  147.27 106.68 270 top
R1814  10MR3J-L1-GP  [R603H22]  169.88 145.19 270 top
R1816  0R0402-PAD-2-GP  [0R0402-PAD-1]  147.17 122.35 0 bottom
R1818  0R0402-PAD-2-GP  [0R0402-PAD-1]  68.55 210.06 270 top
R1822  0R0402-PAD-2-GP  [0R0402-PAD-1]  68.53 211.18 270 top
R1901  8K2R2F-1-GP  [R402H16]  162.51 146.3 180 top
R1902  10KR2J-3-GP  [R402H16]  169.34 131.98 270 top
R1905  10KR2J-3-GP  [R402H16]  162.26 153.47 180 top
R1906  2K2R2J-2-GP  [R402H16]  163.7 90.17 90 top
R1907  2K2R2J-2-GP  [R402H16]  163.68 93.42 90 top
R1908  2K2R2J-2-GP  [R402H16]  163.68 92.4 90 top
R1910  10KR2J-3-GP  [R402H16]  184.33 17.4 270 top
R1911  10KR2J-3-GP  [R402H16]  159.97 141.81 90 top
R1912  10KR2J-3-GP  [R402H16]  150.82 145.14 270 top
R1913  33R2J-2-GP  [R402H16]  185.01 8.76 90 top
R1914  22R2J-2-GP  [R402H16]  164.67 11.15 180 top
R1915  22R2J-2-GP  [R402H16]  185.24 15.95 180 top
R1916  22R2J-2-GP  [R402H16]  169.16 10.29 180 top
R1917  10KR2J-3-GP  [R402H16]  153.82 139.7 90 top
R1918  10KR2J-3-GP  [R402H16]  153.82 138.66 90 top
R1919  10KR2J-3-GP  [R402H16]  160.27 139.06 0 top
R2001  10KR2J-3-GP  [R402H16]  169.11 126.06 0 top
R2002  10KR2J-3-GP  [R402H16]  170.23 10.9 0 top
R2003  1KR2J-1-GP  [R402H16]  167.64 105.03 90 top
R2004  0R2J-2-GP  [R402H16]  167.31 129.51 270 top
R2005  2K2R2J-2-GP  [R402H16]  169.7 95.22 270 top
R2006  0R0402-PAD-2-GP  [0R0402-PAD-1]  152.91 102.74 0 top
R2007  10KR2J-3-GP  [R402H16]  54.66 218.85 180 top
R2009  499R2F-2-GP  [R402H16]  167.51 127.89 90 top
R2010  499R2F-2-GP  [R402H16]  168 123.34 180 top
R2011  51R2F-2-GP  [R402H16]  154.94 105.92 0 top
R2012  1KR2J-1-GP  [R402H16]  157.61 12.47 180 top
R2013  1KR2J-1-GP  [R402H16]  158.7 12.47 180 top
R2014  1KR2J-1-GP  [R402H16]  177.29 59.44 180 top
R2015  10KR2J-3-GP  [R402H16]  168.12 134.59 180 top
R2017  33R2J-2-GP  [R402H16]  61.54 251.79 270 top
R2019  33R2J-2-GP  [R402H16]  64.64 237.95 270 top
R2020  33R2J-2-GP  [R402H16]  61.54 250.77 270 top
R2021  1K5R2F-2-GP  [R402H16]  155.53 100.97 90 top
R2022  33R2J-2-GP  [R402H16]  63.5 247.14 270 top
R2024  100R2F-L1-GP-U  [R402H14]  156.03 102.62 0 top
R2025  30R2J-1-GP  [R402H16]  158.33 107.96 225 top
R2026  51R2F-2-GP  [R402H16]  155.02 102.62 0 top
R2027  30R2J-1-GP  [R402H16]  158.75 105.28 180 top
R2028  51R2F-2-GP  [R402H16]  156.08 105.33 0 top
R2032  33R2J-2-GP  [R402H16]  52.48 218.8 0 top
R2033  33R2J-2-GP  [R402H16]  49.96 218.16 90 top
R2034  0R0402-PAD-2-GP  [0R0402-PAD-1]  194.46 20.47 270 bottom
R2035  4K7R2J-2-GP  [R402H16]  191.29 20.4 270 top
R2036  0R0402-PAD-2-GP  [0R0402-PAD-1]  166.57 152.75 90 top
R2037  1KR2J-1-GP  [R402H16]  190.68 22.12 0 top
R2038  1KR2J-1-GP  [R402H16]  191.72 22.07 0 top
R2039  0R0402-PAD-2-GP  [0R0402-PAD-1]  194.46 21.64 270 bottom
R2040  30K1R2F-L-GP  [R402H16]  165.61 151.71 270 top
R2041  10KR2J-3-GP  [R402H16]  157.1 147.73 270 top
R2042  30K1R2F-L-GP  [R402H16]  165.69 149.48 90 top
R2043  4K7R2J-2-GP  [R402H16]  167.85 149.1 0 top
R2044  10KR2J-3-GP  [R402H16]  36.53 236.3 90 top
R2045  100KR2J-1-GP  [R402H16]  91.87 27.2 90 top
R2046  100KR2J-1-GP  [R402H16]  27.38 36.17 270 top
R2047  100KR2J-1-GP  [R402H16]  160.45 8.64 0 top
R2048  100KR2J-1-GP  [R402H16]  36.52 237.36 90 top
R2052  100KR2J-1-GP  [R402H16]  60.07 252.04 180 top
R2053  100KR2J-1-GP  [R402H16]  62.71 237.95 270 top
R2054  100KR2J-1-GP  [R402H16]  167.31 118.54 90 top
R2055  100KR2J-1-GP  [R402H16]  173.86 37.67 270 top
R2101  0R0603-PAD-2-GP-U  [0R0603-PAD-1-U]  167.44 117.82 180 bottom
R2102  0R3J-0-U-GP  [R603H22]  167.78 119.84 270 top
R2201  30D1R2F-L-GP  [R402H16]  157.23 105.28 0 top
R2301  4K7R2J-2-GP  [R402H16]  157.1 145.54 90 top
R2302  4K7R2J-2-GP  [R402H16]  62.99 248.28 90 top
R2303  10KR2J-3-GP  [R402H16]  166.65 108 180 top
R2304  20KR2J-L2-GP  [R402H16]  61.98 249.3 270 top
R2305  10KR2J-3-GP  [R402H16]  162.96 108.46 90 top
R2306  0R2J-2-GP  [R402H16]  183.08 10.67 270 top
R2307  4K7R2J-2-GP  [R402H16]  184.56 10.31 180 top
R2309  20KR2J-L2-GP  [R402H16]  183.08 9.6 270 top
R2310  20KR2J-L2-GP  [R402H16]  165.53 108.03 0 top
R2312  10KR2J-3-GP  [R402H16]  164.47 108.03 0 top
R2313  20KR2J-L2-GP  [R402H16]  166.96 146.69 180 top
R2314  10KR2J-3-GP  [R402H16]  167.44 125.48 90 top
R2317  20KR2J-L2-GP  [R402H16]  166.7 144.53 180 top
R2318  1KR2J-1-GP  [R402H16]  169.27 134.57 180 top
R2323  20KR2J-L2-GP  [R402H16]  166.88 123.37 180 top
R2324  2K2R2J-2-GP  [R402H16]  163.7 91.31 90 top
R2325  1KR2J-1-GP  [R402H16]  165.94 146.69 180 top
R2326  4K7R2J-2-GP  [R402H16]  164.9 144.48 0 top
R2327  2K2R2J-2-GP  [R402H16]  163.68 94.43 90 top
R2328  4K7R2J-2-GP  [R402H16]  163.27 140.97 180 top
R2329  2K2R2J-2-GP  [R402H16]  162.5 103.99 45 top
R2401  22R2J-2-GP  [R402H16]  182.5 23.85 270 top
R2402  8K2R2F-1-GP  [R402H16]  157.58 36.25 270 top
R2403  30KR2F-GP  [R402H16]  156.97 41.53 270 top
R2404  9K1R2F-1-GP  [R402H16]  155.47 31.83 180 top
R2405  30KR2F-GP  [R402H16]  160.38 36.14 270 top
R2406  100KR2J-1-GP  [R402H16]  184.05 23.5 0 top
R2407  22R2J-2-GP  [R402H16]  186.18 21.34 0 top
R2408  680R2F-GP  [R402H16]  154.86 36.27 270 top
R2409  6K8R2F-2-GP  [R402H16]  155.45 34.52 180 top
R2410  100KR2J-1-GP  [R402H16]  185.12 23.5 0 top
R2411  10KR2F-2-GP  [R402H16]  184.1 18.87 180 top
R2412  30KR2F-GP  [R402H16]  162.1 38.99 270 top
R2413  10KR2F-2-GP  [R402H16]  163.17 37.95 270 top
R2414  9K1R2F-1-GP  [R402H16]  164.06 38.99 90 top
R2415  2KR2F-3-GP  [R402H16]  167.56 37.74 90 top
R2416  2KR2F-3-GP  [R402H16]  184.53 20.35 90 top
R2417  9K1R2F-1-GP  [R402H16]  162.28 36.25 270 top
R2419  10KR2J-3-GP  [R402H16]  164.97 34.54 180 top
R2421  10KR2J-3-GP  [R402H16]  172.47 35.2 180 top
R2422  0R0402-PAD-2-GP  [0R0402-PAD-1]  173.1 10.85 180 top
R2423  7K15R2F-L-GP  [R402H16]  164.06 40.06 270 top
R2424  33KR2F-GP  [R402H16]  169.7 37.74 90 top
R2425  10KR2J-3-GP  [R402H16]  174.62 34.16 180 top
R2426  0R0402-PAD-2-GP  [0R0402-PAD-1]  174.19 10.87 180 top
R2427  10KR2J-3-GP  [R402H16]  173.51 35.2 180 top
R2428  43D2R2F-GP  [R402H16]  177.85 11.3 180 top
R2429  160R2F-GP  [R402H16]  159.74 31.5 270 top
R2430  10KR2J-3-GP  [R402H16]  178.89 11.3 180 top
R2431  4K7R2J-2-GP  [R402H16]  183.08 11.73 90 top
R2432  10KR2J-3-GP  [R402H16]  166.01 34.54 180 top
R2433  33R2J-2-GP  [R402H16]  180.72 30.23 0 top
R2434  0R0402-PAD-2-GP  [0R0402-PAD-1]  180.72 32.26 0 top
R2435  10KR2J-3-GP  [R402H16]  158.62 18.06 90 top
R2438  0R0402-PAD-2-GP  [0R0402-PAD-1]  176.17 36.63 270 top
R2439  0R0402-PAD-2-GP  [0R0402-PAD-1]  183.51 32.26 180 top
R2442  20KR2J-L2-GP  [R402H16]  181.91 29.03 0 top
R2446  330KR2F-L-GP  [R402H16]  183.06 12.78 270 top
R2448  10KR2J-3-GP  [R402H16]  182.5 22.83 270 top
R2449  10KR2J-3-GP  [R402H16]  182.37 26.29 270 top
R2450  1KR2J-1-GP  [R402H16]  160.66 17.78 90 top
R2452  10KR2J-3-GP  [R402H16]  160.2 12.9 90 top
R2453  10KR2J-3-GP  [R402H16]  160.15 11.81 270 top
R2458  75R2J-1-GP  [R402H16]  183.77 14.2 90 top
R2462  10KR2J-3-GP  [R402H16]  183.77 16.33 90 top
R2463  10KR2J-3-GP  [R402H16]  158.88 20.57 0 top
R2464  10KR2J-3-GP  [R402H16]  158.62 19.1 270 top
R2465  30KR2F-GP  [R402H16]  157.23 27.3 270 top
R2466  20KR2F-L-GP  [R402H16]  171.3 5.16 180 top
R2467  100KR2J-1-GP  [R402H16]  170.26 5.16 180 top
R2468  16KR2F-GP  [R402H16]  168.35 6.68 90 top
R2469  30KR2F-GP  [R402H16]  157.23 26.26 270 top
R2470  30KR2F-GP  [R402H16]  157.43 25.22 270 top
R2471  1K65R2F-GP  [R402H16]  172.8 4.65 90 top
R2472  6K8R2F-2-GP  [R402H16]  168.38 8.69 270 top
R2473  30KR2F-GP  [R402H16]  157.23 31.47 270 top
R2474  47KR2J-2-GP  [R402H16]  181.86 32.26 0 top
R2475  100KR2J-1-GP  [R402H16]  176.35 11.05 270 top
R2476  10KR2J-3-GP  [R402H16]  183.77 15.29 90 top
R2477  10KR2J-3-GP  [R402H16]  174.62 36.2 0 top
R2478  10KR2J-3-GP  [R402H16]  34.52 173.25 270 top
R2501  1KR2J-1-GP  [R402H16]  166.19 160.16 270 top
R2502  1KR2J-1-GP  [R402H16]  166.67 163.75 180 top
R2503  0R0603-PAD-2-GP-U  [0R0603-PAD-1-U]  165.86 161.29 90 top
R2504  1K5R2F-2-GP  [R402H16]  52.88 262.66 270 top
R2505  45K3R2F-L-GP  [R402H16]  50.09 260.48 270 top
R2506  1KR2J-1-GP  [R402H16]  46.15 258.52 180 top
R2507  33R2J-2-GP  [R402H16]  172.95 170.27 270 top
R2601  4K7R2J-2-GP  [R402H16]  11.05 137.82 0 top
R2602  20KR2J-L2-GP  [R402H16]  13 137.64 180 top
R2603  2K2R2J-2-GP  [R402H16]  13.54 133.82 270 top
R2604  8K2R2F-1-GP  [R402H16]  14.15 137.64 0 top
R2605  100R2F-L1-GP-U  [R402H14]  11.51 133.82 90 top
R2611  9K53R2F-GP  [R402H16]  183.11 6.53 0 top
R2612  0R2J-2-GP  [R402H16]  175.95 9.45 270 top
R2613  10K5R2F-GP  [R402H16]  176.66 4.47 270 top
R2614  100R2F-L1-GP-U  [R402H14]  107.29 257.62 270 top
R2615  4K7R2J-2-GP  [R402H16]  107.31 255.4 270 top
R2616  2K2R2J-2-GP  [R402H16]  107.31 256.54 270 top
R2617  8K2R2F-1-GP  [R402H16]  107.31 253.11 270 top
R2618  20KR2J-L2-GP  [R402H16]  107.31 254.25 90 top
R2619  100KR2J-1-GP  [R402H16]  174.75 4.47 270 top
R2701  10KR2J-3-GP  [R402H16]  74.17 265.56 180 top
R2702  47KR2J-2-GP  [R402H16]  65.41 250.12 270 top
R2703  33R2J-2-GP  [R402H16]  63.02 251 180 top
R2704  4K7R2J-2-GP  [R402H16]  67.34 249.91 90 top
R2705  0R0603-PAD-2-GP-U  [0R0603-PAD-1-U]  59.05 277.37 90 top
R2706  100KR2F-L1-GP  [R402H16]  59.59 258.47 180 top
R2707  100KR2F-L1-GP  [R402H16]  58.47 258.67 180 top
R2708  0R0603-PAD-2-GP-U  [0R0603-PAD-1-U]  73.86 277.27 270 top
R2709  100KR2F-L1-GP  [R402H16]  57.3 259.38 180 top
R2710  200KR2F-L-GP  [R402H16]  56.21 259.38 180 top
R2711  100KR2F-L1-GP  [R402H16]  58.83 260.17 270 top
R2712  200KR2F-L-GP  [R402H16]  58.83 261.19 270 top
R2714  220KR2F-GP  [R402H16]  52.83 264.8 0 top
R2715  0R2J-2-GP  [R402H16]  48.16 261.54 90 top
R2716  10KR2J-3-GP  [R402H16]  51.82 264.8 180 top
R2717  10KR2J-3-GP  [R402H16]  67.26 244.5 0 top
R2718  1KR2J-1-GP  [R402H16]  66.62 237.95 90 top
R2719  1KR2J-1-GP  [R402H16]  62.61 243.59 0 top
R2901  2K2R2J-2-GP  [R402H16]  72.87 255.4 180 top
R2902  1KR2J-1-GP  [R402H16]  73.89 256.54 0 top
R2903  4K7R2J-2-GP  [R402H16]  64.9 267.97 270 top
R2904  4K7R2J-2-GP  [R402H16]  66.93 267.97 90 top
R2905  10R2F-L-GP  [R402H14]  62.97 268.45 270 top
R2906  10R2F-L-GP  [R402H14]  68.83 267.97 90 top
R2907  22KR2J-GP  [R402H16]  68.83 268.99 270 top
R2908  1KR2J-1-GP  [R402H16]  60.2 267.46 180 top
R2909  22KR2J-GP  [R402H16]  62.89 269.49 90 top
R2910  1KR2J-1-GP  [R402H16]  59.18 267.46 180 top
R3001  75R2F-2-GP  [R402H16]  23.62 17.4 270 top
R3002  75R2F-2-GP  [R402H16]  20.83 17.4 90 top
R3003  22KR2J-GP  [R402H16]  23.62 16.38 90 top
R3004  22KR2J-GP  [R402H16]  20.83 16.38 270 top
R3005  75R2F-2-GP  [R402H16]  26.42 19.18 90 top
R3006  75R2F-2-GP  [R402H16]  29.34 19.18 270 top
R3007  22KR2J-GP  [R402H16]  26.42 18.16 270 top
R3008  1KR2J-1-GP  [R402H16]  31.52 21.21 180 top
R3009  22KR2J-GP  [R402H16]  29.34 18.16 90 top
R3010  1KR2J-1-GP  [R402H16]  31.45 19.13 180 top
R3011  2K2R2J-2-GP  [R402H16]  67.53 252.64 90 top
R3012  2K2R2J-2-GP  [R402H16]  69.41 252.64 90 top
R3013  75R2F-2-GP  [R402H16]  16.05 24.63 0 top
R3014  75R2F-2-GP  [R402H16]  16.52 22.27 270 top
R3015  22KR2J-GP  [R402H16]  14.99 22.73 180 top
R3016  22KR2J-GP  [R402H16]  14.99 24.64 0 top
R3101  2K49R2F-GP  [R402H16]  134.19 29.31 0 top
R3102  0R0402-PAD-2-GP  [0R0402-PAD-1]  142.75 18.41 90 top
R3103  1KR2F-3-GP  [R402H16]  143.87 22.71 270 top
R3104  1MR3F-GP  [R603H22]  138.16 30.53 90 top
R3105  0R0603-PAD-2-GP-U  [0R0603-PAD-1-U]  137.97 17.65 270 top
R3106  15KR2F-GP  [R402H16]  143.87 23.75 90 top
R3201  249R2F-GP  [R402H16]  112.9 29.34 90 top
R3202  249R2F-GP  [R402H16]  112.9 30.48 90 top
R3203  0R1210-PAD-GP  [0R1210-4P-PAD]  127.25 26.67 0 top
R3204  510R3J-2-GP  [R603H22]  113.28 28.07 90 top
R3205  0R1210-PAD-GP  [0R1210-4P-PAD]  127.25 24.51 0 top
R3206  0R1210-PAD-GP  [0R1210-4P-PAD]  127.25 22.23 0 top
R3207  0R1210-PAD-GP  [0R1210-4P-PAD]  127.25 20.07 0 top
R3301  0R0402-PAD-2-GP  [0R0402-PAD-1]  40.62 262.66 270 top
R3302  6K2R2F-GP  [R402H16]  33.48 256.62 270 top
R3303  0R1210-PAD-GP  [0R1210-4P-PAD]  35.43 252.86 270 top
R3801  0R1210-PAD-GP  [0R1210-4P-PAD]  83.81 261.76 90 top
R3802  0R1210-PAD-GP  [0R1210-4P-PAD]  102.45 261.13 45 top
R3804  0R1210-PAD-GP  [0R1210-4P-PAD]  81.66 261.75 90 top
R3806  0R1210-PAD-GP  [0R1210-4P-PAD]  100.93 262.65 45 top
R3807  4K7R2J-2-GP  [R402H16]  77.44 257.05 90 top
R3808  4K7R2J-2-GP  [R402H16]  78.23 265.94 90 top
R3809  0R2J-2-GP  [R402H16]  77.44 260.22 90 top
R3810  0R2J-2-GP  [R402H16]  76.71 261.75 180 top
R3811  10KR2J-3-GP  [R402H16]  80.52 267.84 0 top
R3812  10KR2J-3-GP  [R402H16]  77.44 259.08 90 top
R3813  0R0402-PAD-2-GP  [0R0402-PAD-1]  79.65 259.21 270 top
R3814  10KR2J-3-GP  [R402H16]  80.14 266.19 270 top
R3815  10KR2J-3-GP  [R402H16]  79.38 267.84 180 top
R3816  22KR2F-GP  [R402H16]  80.16 257.68 0 top
R3817  10KR2J-3-GP  [R402H16]  79.02 257.68 0 top
R3818  0R2J-2-GP  [R402H16]  18.67 241.43 270 top
R4001  10KR2J-3-GP  [R402H16]  101.35 30.86 90 top
R4003  20KR2J-L2-GP  [R402H16]  103.76 32.77 270 top
R4005  22KR2J-GP  [R402H16]  96.29 29.06 270 top
R4006  0R0402-PAD-2-GP  [0R0402-PAD-1]  96.77 27.91 270 top
R4007  0R0402-PAD-2-GP  [0R0402-PAD-1]  96.39 30.35 90 top
R4008  0R0402-PAD-2-GP  [0R0402-PAD-1]  185.55 18.85 90 top
R4009  0R0402-PAD-2-GP  [0R0402-PAD-1]  171.58 40.64 0 top
R4010  0R0402-PAD-2-GP  [0R0402-PAD-1]  170.43 40.64 0 top
R4011  22KR2J-GP  [R402H16]  116.08 32.18 180 top
R4013  0R0402-PAD-2-GP  [0R0402-PAD-1]  102.23 33.27 180 top
R4014  249R2F-GP  [R402H16]  108.41 33.17 270 top
R4015  0R0402-PAD-2-GP  [0R0402-PAD-1]  116.08 34.09 0 top
R4016  249R2F-GP  [R402H16]  108.41 32.03 270 top
R4017  8K2R2F-1-GP  [R402H16]  99.31 175.26 0 top
R4018  8K2R2F-1-GP  [R402H16]  94.36 176.15 180 top
R4019  0R0402-PAD-2-GP  [0R0402-PAD-1]  101.45 171.53 0 top
R4020  10KR2J-3-GP  [R402H16]  100.43 171.53 180 top
R4021  0R0402-PAD-2-GP  [0R0402-PAD-1]  93.98 170.81 90 top
R4022  10KR2J-3-GP  [R402H16]  93.98 173.99 270 top
R4023  1KR2J-1-GP  [R402H16]  93.98 172.85 270 top
R4024  0R0402-PAD-2-GP  [0R0402-PAD-1]  29.46 173.99 90 top
R4025  0R0402-PAD-2-GP  [0R0402-PAD-1]  23.88 170.69 90 top
R4201  0R0402-PAD-2-GP  [0R0402-PAD-1]  8.42 222.85 0 top
R4202  0R0402-PAD-2-GP  [0R0402-PAD-1]  6.45 222.83 0 top
R4203  47KR2J-2-GP  [R402H16]  42.11 193.12 0 top
R4204  10KR2J-3-GP  [R402H16]  40.61 192.68 270 top
R4205  4K7R2J-2-GP  [R402H16]  39.62 188.21 0 top
R4206  100KR2J-1-GP  [R402H16]  47.96 193.83 270 top
R4207  10KR2J-3-GP  [R402H16]  40.61 193.75 270 top
R4220  10KR2J-3-GP  [R402H16]  184.48 188.72 90 top
R4221  309KR2F-GP  [R402H16]  185.98 189.28 180 top
R4222  10KR2J-3-GP  [R402H16]  25.73 41.1 90 top
R4223  309KR2F-GP  [R402H16]  25.71 42.27 270 top
R4224  22KR2F-GP  [R402H16]  27.38 35.08 270 top
R4225  22KR2F-GP  [R402H16]  186.44 186.08 180 top
R4301  4K7R2J-2-GP  [R402H16]  168.66 189.36 0 top
R4302  0R0402-PAD-2-GP  [0R0402-PAD-1]  167.13 188.98 90 top
R4801  10KR2J-3-GP  [R402H16]  157.12 188.98 180 top
R4802  47KR2J-2-GP  [R402H16]  44.7 174.75 180 top
R4803  10KR2J-3-GP  [R402H16]  152.22 189.56 270 top
R5001  0R2J-2-GP  [R402H16]  41.61 174.24 0 top
R5002  0R2J-2-GP  [R402H16]  42.62 174.24 0 top
R5003  0R0402-PAD-2-GP  [0R0402-PAD-1]  30.35 175.39 90 top
R5101  0R0402-PAD-2-GP  [0R0402-PAD-1]  194.13 189.31 90 top
R5601  470R2J-2-GP  [R402H16]  79.38 25.07 180 top
R5602  470R2J-2-GP  [R402H16]  82.3 25.07 180 top
R5603  470R2J-2-GP  [R402H16]  75.31 25.2 0 top
R5604  470R2J-2-GP  [R402H16]  78.23 25.2 0 top
R5605  470R2J-2-GP  [R402H16]  72.39 22.89 180 top
R5606  470R2J-2-GP  [R402H16]  75.31 22.89 180 top
R5607  470R2J-2-GP  [R402H16]  70.36 25.7 0 top
R5608  470R2J-2-GP  [R402H16]  73.41 25.53 0 top
R5609  20KR2F-L-GP  [R402H16]  65.51 15.82 0 top
R5610  1MR2J-1-GP  [R402H16]  65.15 17.65 90 top
R5901  4K7R2J-2-GP  [R402H16]  58.95 12.52 270 top
R5902  4K7R2J-2-GP  [R402H16]  60.86 12.52 90 top
R5903  4K7R2J-2-GP  [R402H16]  54.71 15.19 270 top
R5904  4K7R2J-2-GP  [R402H16]  56.26 14.73 0 top
R5905  4K7R2J-2-GP  [R402H16]  57.89 24.66 0 top
R5906  4K7R2J-2-GP  [R402H16]  56.87 24.66 0 top
R5907  4K7R2J-2-GP  [R402H16]  55.85 24.66 0 top
R5908  4K7R2J-2-GP  [R402H16]  59.16 13.56 90 top
R5909  4K7R2J-2-GP  [R402H16]  61.06 13.56 270 top
R5910  100KR2J-1-GP  [R402H16]  59.84 15.16 0 top
R5911  0R0402-PAD-2-GP  [0R0402-PAD-1]  58.8 15.16 0 top
R5912  0R0402-PAD-2-GP  [0R0402-PAD-1]  57.66 15.16 0 top
R5913  75R2F-2-GP  [R402H16]  50.93 20.83 180 top
R5914  75R2F-2-GP  [R402H16]  50.93 18.92 180 top
R5915  75R2F-2-GP  [R402H16]  50.93 16.89 180 top
R5916  47R2F-GP  [R402H16]  41.66 18.92 270 top
R5917  47R2F-GP  [R402H16]  40.77 17.02 270 top
R5918  10KR2F-2-GP  [R402H16]  41.85 26.54 0 top
R5919  100KR2J-1-GP  [R402H16]  42.87 26.54 0 top
R6201  0R0402-PAD-2-GP  [0R0402-PAD-1]  137.44 4.27 90 top
R6202  0R2J-2-GP  [R402H16]  132.05 4.98 0 top
R6203  0R2J-2-GP  [R402H16]  133.22 4.95 0 top
R6301  60K4R2F-GP  [R402H16]  53.54 218.82 180 top
R6302  75KR2F-GP  [R402H16]  49.99 217.07 270 top
R6303  0R2J-2-GP  [R402H16]  64.75 230.4 270 top
R6304  10KR2J-3-GP  [R402H16]  66.9 236.12 90 top
R6306  10KR2J-3-GP  [R402H16]  37.19 245.21 0 top
R6308  10KR2J-3-GP  [R402H16]  149.55 154.18 90 top
R6309  0R3J-0-U-GP  [R603H22]  39.5 233.04 0 top
